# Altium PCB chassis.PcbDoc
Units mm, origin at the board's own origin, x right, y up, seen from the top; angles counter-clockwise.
Board outline 100 x 100 mm, 2 copper layers (Top Layer, Bottom Layer); 8 components, 1 nets, 8 pads, 128 vias.
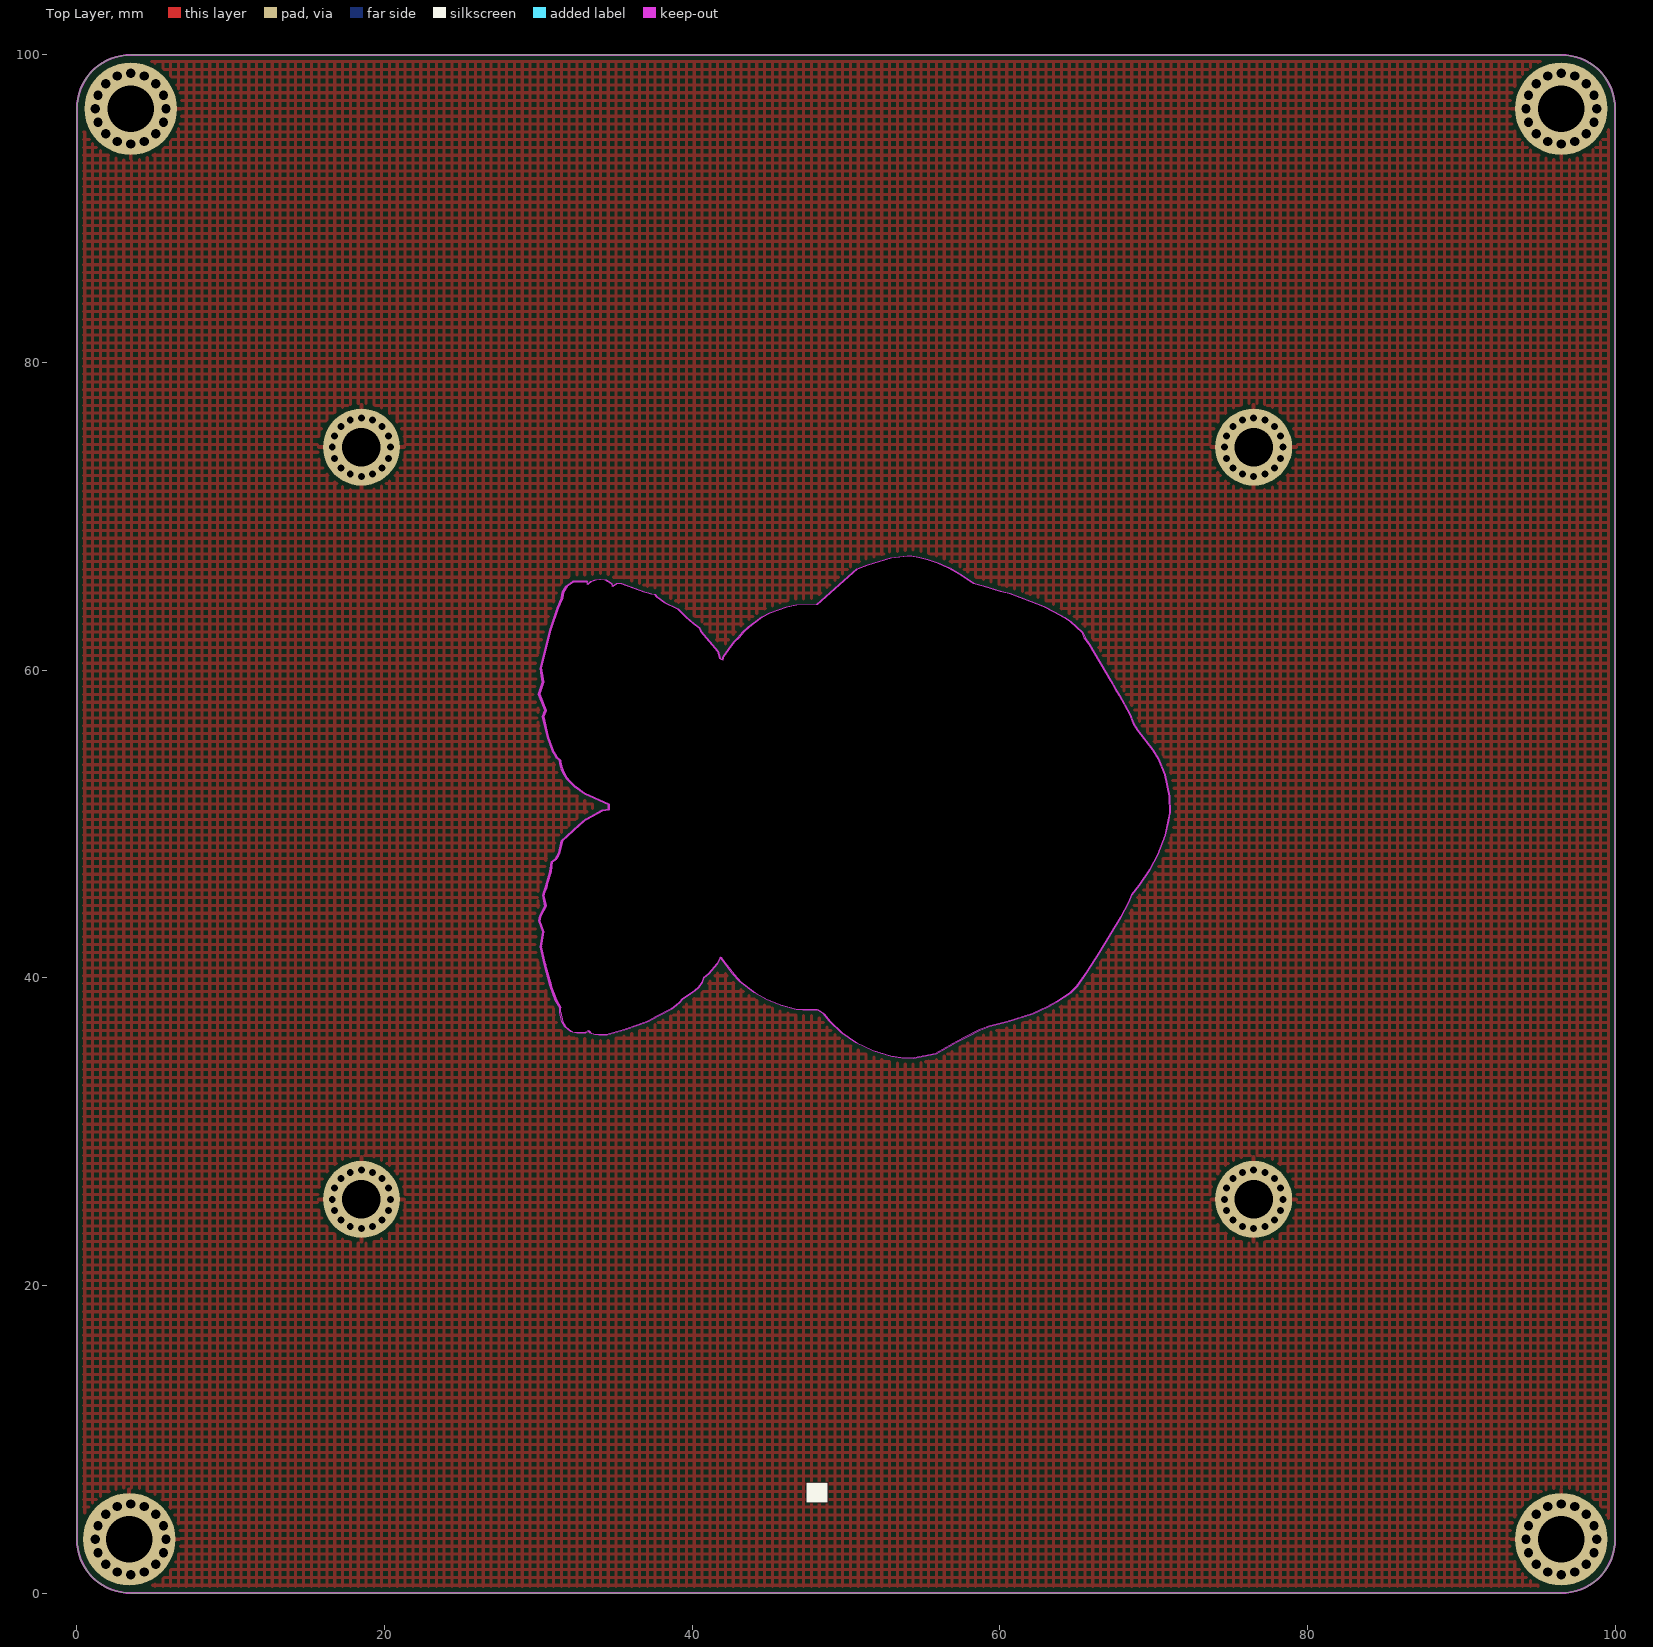
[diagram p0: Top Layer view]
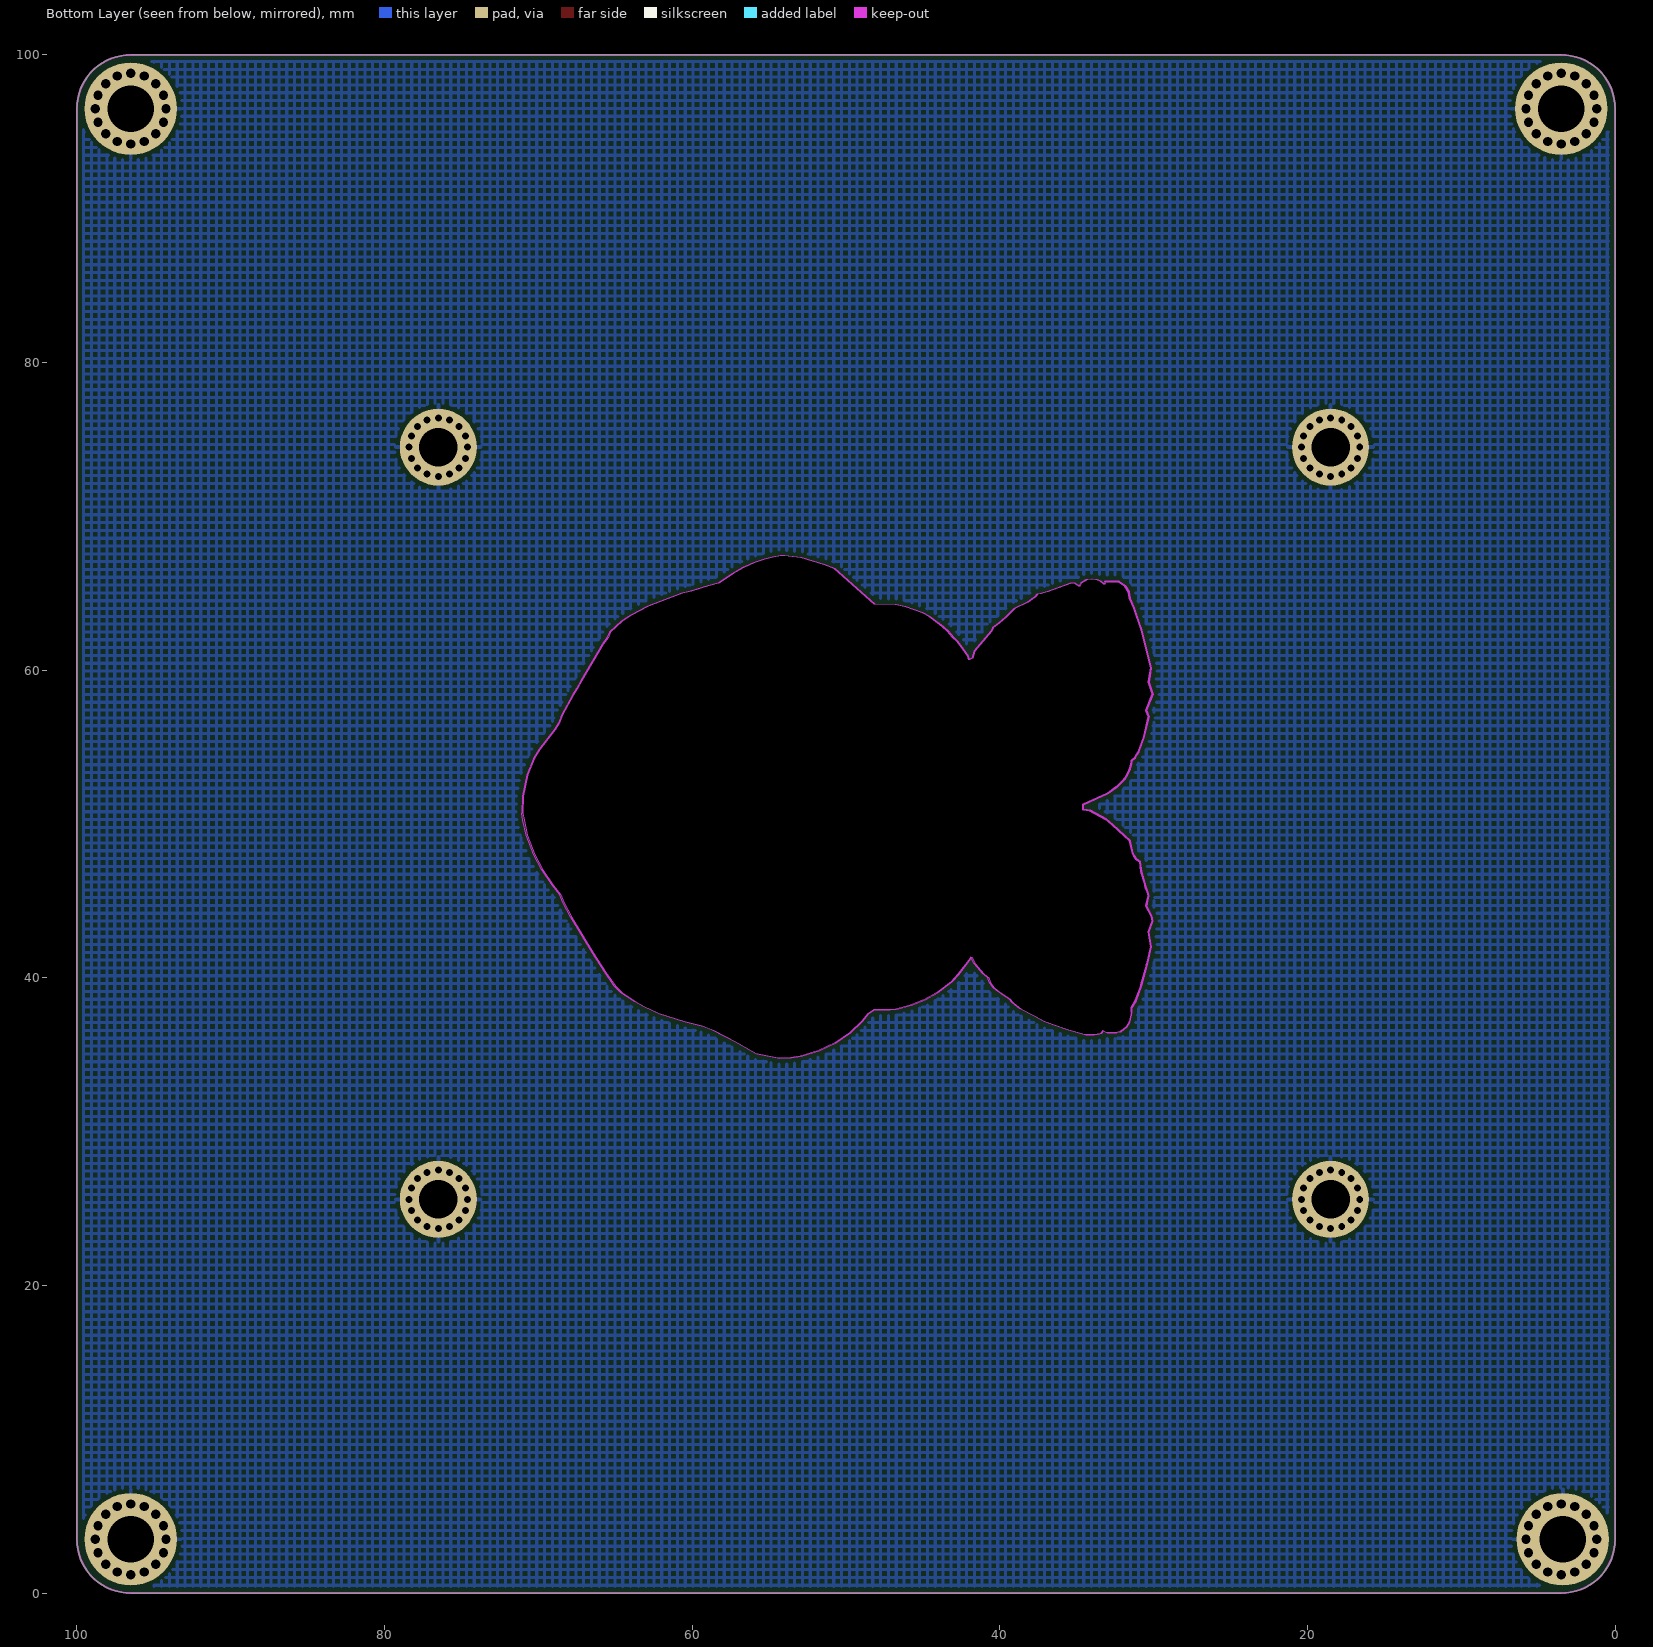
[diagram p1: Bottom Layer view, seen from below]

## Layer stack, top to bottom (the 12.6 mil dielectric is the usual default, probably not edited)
Top Solder: solder mask 0.0102, Solder Resist, Dk 3.5
Top Layer: signal copper 0.0356
Dielectric 1: dielectric 0.32, FR-4, Dk 4.8
Bottom Layer: signal copper 0.0356
Bottom Solder: solder mask 0.0102, Solder Resist, Dk 3.5

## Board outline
3.5,0 cw(c3.5,3.5) 0,3.5 0,96.5 cw(c3.5,96.5) 3.5,100 96.5,100 cw(c96.5,96.5) 100,96.5 100,3.5 cw(c96.5,3.5) 96.5,0
cut-out: 57.8,36.18 57.16,35.83 55.79,35.07 54.32,34.77 53.55,34.79 52.9,34.9 51.73,35.25 50.62,35.79 49.68,36.44 48.92,37.17 48.53,37.65 48.13,37.92 47.11,37.92 46.71,37.95 45.75,38.21 44.84,38.58 44.04,39.03 43.1,39.76 42.65,40.23 41.95,41.14 41.82,41.33 41.6,40.93 41.05,40.28 40.72,39.99 40.61,39.71 40.39,39.4 40.12,39.17 39.84,38.95 39.31,38.62 39.17,38.42 38.93,38.21 38.63,37.98 37.69,37.51 37.11,37.18 36.48,36.95 35.55,36.64 34.4,36.29 33.86,36.29 33.61,36.32 33.38,36.39 33.25,36.55 33.01,36.43 32.41,36.43 32.12,36.51 31.9,36.65 31.72,36.83 31.53,37.13 31.38,37.75 31.38,38.06 31.11,38.52 30.74,39.53 30.38,40.86 30.12,42.02 30.27,42.99 30.01,43.7 30.08,44.02 30.42,44.66 30.27,45.36 30.34,45.59 30.45,45.88 30.53,46.21 30.75,46.91 30.83,47.54 31.09,47.73 31.2,47.91 31.31,48.14 31.49,48.91 31.83,49.25 32.61,49.96 33.09,50.33 34.08,50.88 34.53,50.95 34.53,51.26 32.93,51.99 32.37,52.4 31.85,52.92 31.67,53.18 31.53,53.47 31.42,53.8 31.37,54.14 31.16,54.29 31.05,54.51 30.92,54.68 30.57,55.67 30.26,56.98 30.42,57.39 30,58.44 30.26,59.22 30.19,59.64 30.11,60.14 30.73,62.61 31.22,64.05 31.49,64.69 31.56,65.1 31.79,65.46 32.2,65.76 33.08,65.77 33.18,65.59 33.41,65.79 33.68,65.88 33.97,65.91 34.33,65.87 34.71,65.66 34.79,65.47 35.09,65.65 35.34,65.65 36.22,65.33 36.85,65.09 37.11,65.02 37.31,64.98 37.53,64.95 37.67,64.77 37.89,64.62 38.15,64.43 39.04,63.99 39.18,63.82 39.59,63.44 40.03,63.06 40.42,62.76 40.52,62.54 41.64,61.24 41.75,60.77 41.95,60.68 42.03,60.89 42.34,61.35 42.71,61.84 43.01,62.15 43.3,62.5 43.66,62.83 44.53,63.47 45,63.73 46.11,64.13 46.74,64.25 48.1,64.29 50.71,66.61 51.39,66.87 52.88,67.31 53.98,67.43 54.21,67.44 54.74,67.35 55.26,67.21 55.94,66.97 56.66,66.66 57.34,66.27 58.28,65.65 58.89,65.48 60.04,65.14 60.62,64.99 61.98,64.49 62.81,64.15 63.51,63.79 64.14,63.43 64.55,63.18 65.31,62.47 65.47,62.12 65.79,61.67 67.18,59.32 67.48,58.79 67.73,58.37 68.4,57.12 68.63,56.56 68.89,56.14 69.92,54.82 70.26,54.23 70.68,53.2 70.97,51.8 71.01,50.69 70.93,50.25 70.71,49.28 70.23,47.99 69.71,47.03 69.02,46.01 68.53,45.39 68.34,44.9 67.82,43.93 66.42,41.63 65.61,40.36 64.98,39.45 64.56,39.03 63.67,38.44 63.07,38.12 62.1,37.68 60.46,37.15 59.28,36.86 58.61,36.58
cut-out: 31.45,38.06

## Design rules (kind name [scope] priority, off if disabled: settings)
Clearance [All] p1: gap=0.254 ignorepadtopadclearanceinfootprint=FALSE except(0: Arc-Hole Track-Hole SMDPad-Hole THPad-Hole Via-Hole Fill-Hole Poly-Hole Region-Hole Text-Hole)
HoleSize [All] p1: absolutevalues=TRUE maxlimit=1000 minlimit=0.45 maxpercent=80.000 minpercent=20.000
HoleToHoleClearance [All] p1: gap=0.1 allowstackedmicrovias=TRUE
PolygonConnect [All] p1: connectstyle=Relief reliefconductorwidth=0.254 reliefentries=4 polygonreliefangle="90 Angle" airgapwidth=0.254
RoutingVias [All] p1: holewidth=0.711 width=1.27 viastyle="Through Hole" minholewidth=0.3 minwidth=0.3 maxholewidth=300 maxwidth=1000
SolderMaskExpansion [All] p1: expansion=0.102 istentingtop=FALSE
Width [All] p1: maxlimit=0.254 minlimit=0.254 preferedwidth=0.254
28 further rules are at their usual default settings.

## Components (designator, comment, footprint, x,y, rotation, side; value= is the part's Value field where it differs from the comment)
J1 "M3" M3#1 96.5,96.5 r0 top
J2 "M2.5" M2.5 76.5,25.6 r0 top
J3 "M3" M3#1 3.5,96.5 r0 top
J4 "M2.5" M2.5 18.5,25.6 r0 top
J5 "M3" M3#1 96.5,3.5 r0 top
J6 "M2.5" M2.5 76.5,74.5 r0 top
J7 "M3" M3#2 3.5,3.5 r0 top
J8 "M2.5" M2.5 18.5,74.5 r0 top

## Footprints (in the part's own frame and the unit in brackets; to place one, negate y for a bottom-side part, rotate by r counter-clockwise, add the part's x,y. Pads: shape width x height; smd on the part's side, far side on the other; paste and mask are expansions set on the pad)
M2.5 [mm]
  round 5 hole 2.5: 0(0,0)
M3#1 [mm]
  round 6 hole 3: 0(0,0)
M3#2 [mm]
  round 6 hole 3: 0(-0.1,0)

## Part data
J1 J2 J3 J4 J5 J6 J7 J8: library part Screw_Hole

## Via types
v1: diameter 0.45, hole 0.45, Top Layer to Bottom Layer, 64 vias
v2: diameter 0.6, hole 0.6, Top Layer to Bottom Layer, 64 vias

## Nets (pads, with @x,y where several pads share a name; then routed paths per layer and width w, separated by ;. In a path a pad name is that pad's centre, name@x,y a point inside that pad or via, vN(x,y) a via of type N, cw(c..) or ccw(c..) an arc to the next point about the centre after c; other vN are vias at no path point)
GND: J1.0 J2.0 J3.0 J4.0 J5.0 J6.0 J7.0 J8.0
  other v1: 18.5,23.7 76.5,23.7 17.773,23.845 19.227,23.845 75.773,23.845 77.227,23.845 17.157,24.257 19.843,24.257 75.157,24.257 77.843,24.257 16.745,24.873 20.255,24.873 74.745,24.873 78.255,24.873 16.6,25.6 20.4,25.6 74.6,25.6 78.4,25.6 16.745,26.327 20.255,26.327 74.745,26.327 78.255,26.327 17.157,26.943 19.843,26.943 75.157,26.943 77.843,26.943 17.773,27.355 19.227,27.355 75.773,27.355 77.227,27.355 18.5,27.5 76.5,27.5 18.5,72.6 76.5,72.6 17.773,72.745 19.227,72.745 75.773,72.745 77.227,72.745 17.157,73.157 19.843,73.157 75.157,73.157 77.843,73.157 16.745,73.773 20.255,73.773 74.745,73.773 78.255,73.773 16.6,74.5 20.4,74.5 74.6,74.5 78.4,74.5 16.745,75.227 20.255,75.227 74.745,75.227 78.255,75.227 17.157,75.843 19.843,75.843 75.157,75.843 77.843,75.843 17.773,76.255 19.227,76.255 75.773,76.255 77.227,76.255 18.5,76.4 76.5,76.4
  other v2: 3.5,1.2 96.5,1.2 2.62,1.375 4.38,1.375 95.62,1.375 97.38,1.375 1.874,1.874 5.126,1.874 94.874,1.874 98.126,1.874 1.375,2.62 5.625,2.62 94.375,2.62 98.625,2.62 1.2,3.5 5.8,3.5 94.2,3.5 98.8,3.5 1.375,4.38 5.625,4.38 94.375,4.38 98.625,4.38 1.874,5.126 5.126,5.126 94.874,5.126 98.126,5.126 2.62,5.625 4.38,5.625 95.62,5.625 97.38,5.625 3.5,5.8 96.5,5.8 3.5,94.2 96.5,94.2 2.62,94.375 4.38,94.375 95.62,94.375 97.38,94.375 1.874,94.874 5.126,94.874 94.874,94.874 98.126,94.874 1.375,95.62 5.625,95.62 94.375,95.62 98.625,95.62 1.2,96.5 5.8,96.5 94.2,96.5 98.8,96.5 1.375,97.38 5.625,97.38 94.375,97.38 98.625,97.38 1.874,98.126 5.126,98.126 94.874,98.126 98.126,98.126 2.62,98.625 4.38,98.625 95.62,98.625 97.38,98.625 3.5,98.8 96.5,98.8

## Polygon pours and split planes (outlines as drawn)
GND on Top Layer "Top Layer-No Net" (hatched 90Degree grid 0.508 track 0.203, remove dead copper, pour order 0): 3.5,0 cw(c3.5,3.5) 0,3.5 0,96.5 cw(c3.5,96.5) 3.5,100 96.5,100 cw(c96.5,96.5) 100,96.5 100,3.5 cw(c96.5,3.5) 96.5,0
GND on Bottom Layer "Top Layer-No Net1" (hatched 90Degree grid 0.508 track 0.203, remove dead copper, pour order 1): 3.5,0 cw(c3.5,3.5) 0,3.5 0,96.5 cw(c3.5,96.5) 3.5,100 96.5,100 cw(c96.5,96.5) 100,96.5 100,3.5 cw(c96.5,3.5) 96.5,0

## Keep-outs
Keep-Out Layer:
  lines w0.05: 31.45,38.06 31.45,37.75 31.6,37.13 31.79,36.83 31.97,36.65 32.19,36.51 32.48,36.43 33.08,36.43 33.32,36.55 33.45,36.39 33.68,36.32 33.93,36.29 34.47,36.29 35.62,36.64 36.55,36.95 37.18,37.18 37.76,37.51 38.7,37.98 39,38.21 39.24,38.42 39.38,38.62 39.91,38.95 40.19,39.17 40.46,39.4 40.68,39.71 40.79,39.99 41.12,40.28 41.67,40.93 41.89,41.33 42.02,41.14 42.72,40.23 43.17,39.76 44.11,39.03 44.91,38.58 45.82,38.21 46.78,37.95 47.18,37.92 48.2,37.92 48.6,37.65 48.99,37.17 49.75,36.44 50.69,35.79 51.8,35.25 52.97,34.9 53.62,34.79 54.39,34.77 55.86,35.07 57.23,35.83 57.87,36.18 58.68,36.58 59.35,36.86 60.53,37.15 62.17,37.68 63.14,38.12 63.74,38.44 64.63,39.03 65.05,39.45 65.68,40.36 66.49,41.63 67.89,43.93 68.41,44.9 68.6,45.39 69.09,46.01 69.78,47.03 70.3,47.99 70.78,49.28 71,50.25 71.08,50.69 71.04,51.8 70.75,53.2 70.33,54.23 69.99,54.82 68.96,56.14 68.7,56.56 68.47,57.12 67.8,58.37 67.55,58.79 67.25,59.32 65.86,61.67 65.54,62.12 65.38,62.47 64.62,63.18 64.21,63.43 63.58,63.79 62.88,64.15 62.05,64.49 60.69,64.99 60.11,65.14 58.96,65.48 58.35,65.65 57.41,66.27 56.73,66.66 56.01,66.97 55.33,67.21 54.81,67.35 54.28,67.44 54.05,67.43 52.95,67.31 51.46,66.87 50.78,66.61 48.17,64.29 46.81,64.25 46.18,64.13 45.07,63.73 44.6,63.47 43.73,62.83 43.37,62.5 43.08,62.15 42.78,61.84 42.41,61.35 42.1,60.89 42.02,60.68 41.82,60.77 41.71,61.24 40.59,62.54 40.49,62.76 40.1,63.06 39.66,63.44 39.25,63.82 39.11,63.99 38.22,64.43 37.96,64.62 37.74,64.77 37.6,64.95 37.38,64.98 37.18,65.02 36.92,65.09 36.29,65.33 35.41,65.65 35.16,65.65 34.86,65.47 34.78,65.66 34.4,65.87 34.04,65.91 33.75,65.88 33.48,65.79 33.25,65.59 33.15,65.77
  lines w0.127: 31.45,38.06 31.18,38.52 30.81,39.53 30.45,40.86 30.19,42.02 30.34,42.99 30.08,43.7 30.15,44.02 30.49,44.66 30.34,45.36 30.41,45.59 30.52,45.88 30.6,46.21 30.82,46.91 30.9,47.54 31.16,47.73 31.27,47.91 31.38,48.14 31.56,48.91 31.9,49.25 32.68,49.96 33.16,50.33 34.15,50.88 34.6,50.95 34.6,51.26 33,51.99 32.44,52.4 31.92,52.92 31.74,53.18 31.6,53.47 31.49,53.8 31.44,54.14 31.23,54.29 31.12,54.51 30.99,54.68 30.64,55.67 30.33,56.98 30.49,57.39 30.07,58.44 30.33,59.22 30.26,59.64 30.18,60.14 30.8,62.61 31.29,64.05 31.56,64.69 31.63,65.1 31.86,65.46 32.27,65.76 33.15,65.77 ; 0,3.5 ccw(c3.5,3.5) 3.5,0 96.5,0 ccw(c96.5,3.5) 100,3.5 100,96.5 ccw(c96.5,96.5) 96.5,100 3.5,100 ccw(c3.5,96.5) 0,96.5 0,3.5

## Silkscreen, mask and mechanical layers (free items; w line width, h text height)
Top Overlay:
  text "4" at 60.2,0.97 h60 r90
